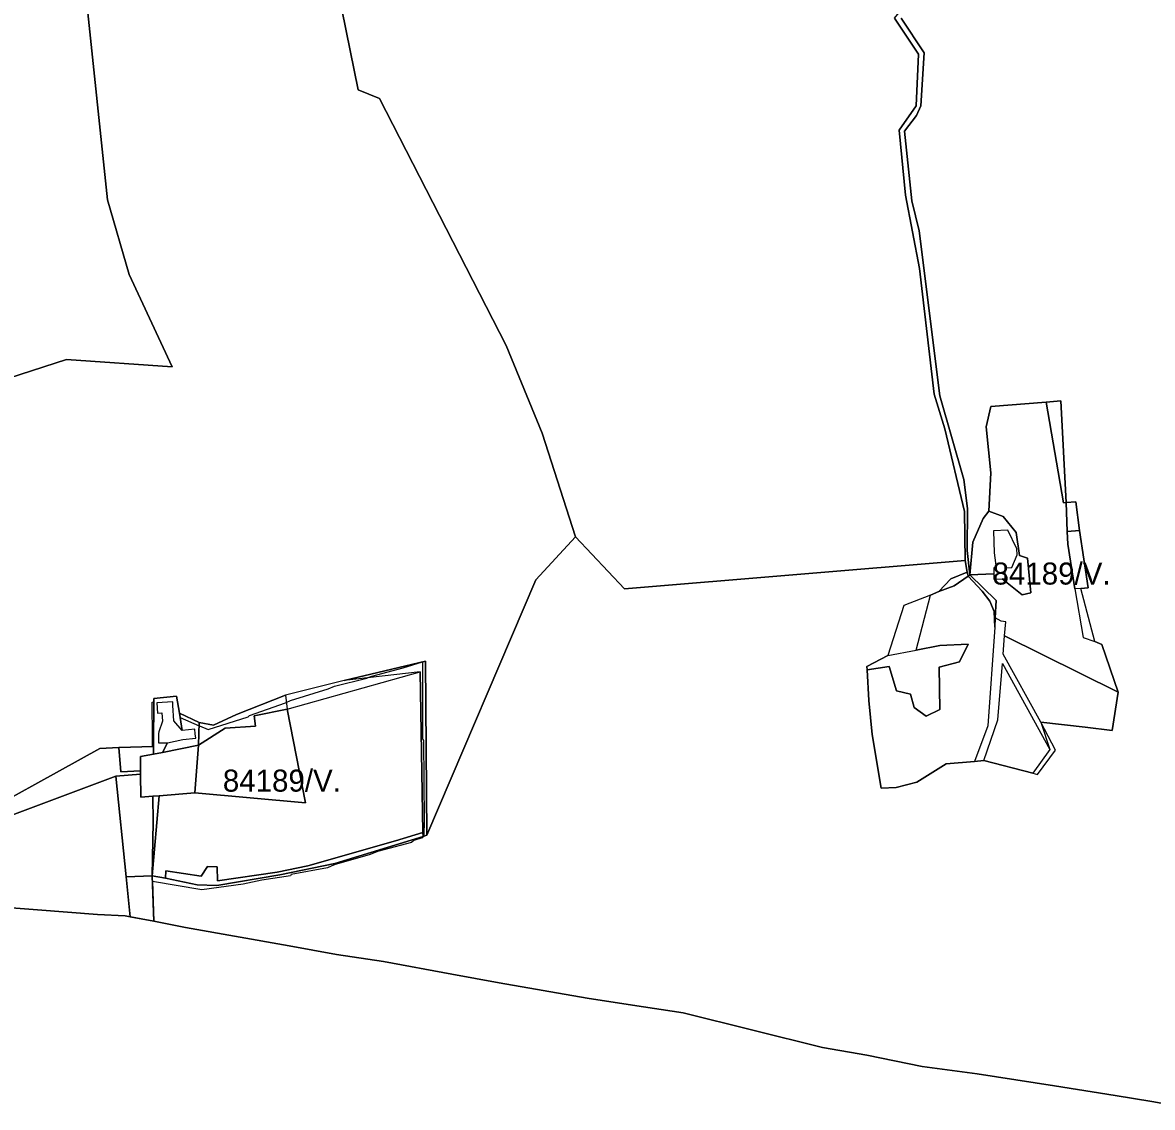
# Model space of a CAD drawing. Extents: x -477304 to -465429, y -1159113 to -1149210.
# Drawn here: x -473443 to -472675, y -1155293 to -1154555 of the extents above; entities that cross this region are included whole.
import ezdxf

# ---------------------------------------------------------------- set-up
doc = ezdxf.new("R2010")
doc.units = 0
for name, color, linetype in [('BPEJ_s', 7, 'Continuous'), ('PUPFL_s', 7, 'Continuous'), ('trav_porost_s', 7, 'Continuous'), ('voda_s', 7, 'Continuous'), ('zahrada_s', 7, 'Continuous')]:
    doc.layers.add(name, color=color, linetype=linetype)

msp = doc.modelspace()

# ---------------------------------------------------------------- linework, layer by layer
at = {"layer": 'BPEJ_s'}
msp.add_lwpolyline([(-472746.83, -1154812.93), (-472735.06, -1154881.5), (-472733.36, -1154881.36), (-472726.59, -1154880.79), (-472724.07, -1154900.37), (-472718.33, -1154939.28), (-472723.38, -1154939.7), (-472727.28, -1154940.03), (-472721.8, -1154973.13), (-472713.74, -1154975.9), (-472708.89, -1154977.79), (-472697.9, -1155010.18), (-472701.86, -1155036.25), (-472720.26, -1155034.13), (-472750.46, -1155030.58), (-472744.27, -1155049.38), (-472755.99, -1155065.45), (-472789.16, -1155056.73), (-472795.52, -1155057.36), (-472814.87, -1155058.96), (-472834.78, -1155071.44), (-472848.82, -1155075.06), (-472859.15, -1155075.63), (-472865.14, -1155039.05), (-472867.53, -1155015.89), (-472868.61, -1154995.04), (-472868.73, -1154992.77), (-472854.56, -1154985.33), (-472835.26, -1154981.63), (-472825.58, -1154944.23), (-472819.91, -1154941.84), (-472809.52, -1154937.87), (-472799.95, -1154931.38), (-472798.78, -1154930.53), (-472796.7, -1154908.14), (-472789.74, -1154892.22), (-472785.74, -1154887.11), (-472784.59, -1154861.16), (-472787.56, -1154829.87), (-472784.53, -1154816.01)], close=True, dxfattribs=at)
for points in [[(-472867.53, -1155015.89), (-472868.61, -1154995.04), (-472868.73, -1154992.77), (-472854.56, -1154985.33), (-472835.26, -1154981.63), (-472825.58, -1154944.23), (-472819.91, -1154941.84), (-472809.52, -1154937.87), (-472799.95, -1154931.38), (-472798.78, -1154930.53), (-472796.7, -1154908.14), (-472789.74, -1154892.22), (-472785.74, -1154887.11), (-472784.59, -1154861.16), (-472787.56, -1154829.87), (-472784.53, -1154816.01), (-472746.83, -1154812.93), (-472735.06, -1154881.5), (-472733.36, -1154881.36), (-472726.59, -1154880.79), (-472724.07, -1154900.37), (-472718.33, -1154939.28), (-472723.38, -1154939.7), (-472727.28, -1154940.03), (-472721.8, -1154973.13), (-472713.74, -1154975.9), (-472708.89, -1154977.79), (-472697.9, -1155010.18), (-472701.86, -1155036.25), (-472720.26, -1155034.13), (-472750.46, -1155030.58), (-472744.27, -1155049.38), (-472755.99, -1155065.45), (-472789.16, -1155056.73), (-472795.52, -1155057.36), (-472814.87, -1155058.96), (-472834.78, -1155071.44), (-472848.82, -1155075.06), (-472859.15, -1155075.63), (-472865.14, -1155039.05), (-472867.53, -1155015.89)], [(-473489.74, -1155103.39), (-473390.35, -1155048.64), (-473377.43, -1155047.9), (-473354.66, -1155047.17), (-473354.66, -1155030.8), (-473354.88, -1155027.39), (-473354.87, -1155017.03), (-473353.66, -1155016.86), (-473353.64, -1155014.55), (-473338.29, -1155012.91), (-473336.36, -1155024.64), (-473335.9, -1155027.51), (-473322.9, -1155033.08), (-473322.57, -1155033.22), (-473316.82, -1155035.69), (-473289.6, -1155026.97), (-473288.75, -1155026.12), (-473264.08, -1155017.61), (-473263.65, -1155017.4), (-473260.68, -1155015.91), (-473235.16, -1155008.04), (-473230.91, -1155006.13), (-473208.8, -1155000.81), (-473207.87, -1155000.41), (-473205.39, -1154999.33), (-473184.16, -1154993.7), (-473170.94, -1154989.74), (-473170.94, -1155042.07), (-473170.68, -1155042.5), (-473170.31, -1155043.13), (-473169.88, -1155097.56), (-473170.09, -1155107.77), (-473170.47, -1155108.3), (-473171.16, -1155109.26), (-473176.9, -1155111.17), (-473178.6, -1155112.45), (-473201.57, -1155118.62), (-473206.67, -1155120.74), (-473216.81, -1155123.64), (-473230.48, -1155127.55), (-473233.1, -1155128.64), (-473235.59, -1155129.67), (-473260.25, -1155134.35), (-473260.89, -1155135.2), (-473280.24, -1155138.18), (-473293, -1155140.94), (-473321.07, -1155144.77), (-473354.67, -1155139.1), (-473353.67, -1155166.14), (-473355.1, -1155165.87), (-473373.26, -1155162.42), (-473392.03, -1155161.46), (-473432.75, -1155158.36), (-473468.65, -1155155.71)], [(-473489.74, -1155103.39), (-473390.35, -1155048.64), (-473377.43, -1155047.9), (-473354.66, -1155047.17), (-473354.66, -1155030.8), (-473354.88, -1155027.39), (-473354.87, -1155017.03), (-473353.66, -1155016.86), (-473353.64, -1155014.55), (-473338.29, -1155012.91), (-473336.36, -1155024.64), (-473335.9, -1155027.51), (-473322.9, -1155033.08), (-473322.57, -1155033.22), (-473316.82, -1155035.69), (-473289.6, -1155026.97), (-473288.75, -1155026.12), (-473264.08, -1155017.61), (-473263.65, -1155017.4), (-473260.68, -1155015.91), (-473235.16, -1155008.04), (-473230.91, -1155006.13), (-473208.8, -1155000.81), (-473207.87, -1155000.41), (-473205.39, -1154999.33), (-473184.16, -1154993.7), (-473170.94, -1154989.74), (-473170.94, -1155042.07), (-473170.68, -1155042.5), (-473170.31, -1155043.13), (-473169.88, -1155097.56), (-473170.09, -1155107.77), (-473170.47, -1155108.3), (-473171.16, -1155109.26), (-473176.9, -1155111.17), (-473178.6, -1155112.45), (-473201.57, -1155118.62), (-473206.67, -1155120.74), (-473216.81, -1155123.64), (-473230.48, -1155127.55), (-473233.1, -1155128.64), (-473235.59, -1155129.67), (-473260.25, -1155134.35), (-473260.89, -1155135.2), (-473280.24, -1155138.18), (-473293, -1155140.94), (-473321.07, -1155144.77), (-473354.67, -1155139.1), (-473353.67, -1155166.14), (-473355.1, -1155165.87)], [(-473355.1, -1155165.87), (-473373.26, -1155162.42), (-473392.03, -1155161.46), (-473432.75, -1155158.36), (-473468.65, -1155155.71)]]:
    msp.add_lwpolyline(points, dxfattribs=at)
at = {"layer": 'PUPFL_s'}
for points in [[(-473245.06, -1154451.04), (-473214.68, -1154600.56), (-473200.2, -1154606.58), (-473114.14, -1154774.45), (-473089.68, -1154834.02), (-473067.01, -1154904.59), (-473093.82, -1154933.76), (-473168.03, -1155107.51), (-473168.97, -1154989.09), (-473224.27, -1155002.26), (-473264.22, -1155012.4), (-473297.53, -1155025.46), (-473313.06, -1155032.8), (-473322.84, -1155031.01), (-473336.36, -1155024.64), (-473338.29, -1155012.91), (-473353.64, -1155014.55), (-473353.96, -1155047.15), (-473377.43, -1155047.9), (-473390.35, -1155048.64), (-473489.74, -1155103.39)], [(-472849.91, -1154551.76), (-472833.75, -1154576.35), (-472835.17, -1154611.5), (-472846.89, -1154627.94), (-472842.6, -1154672.34), (-472833, -1154722.2), (-472823.05, -1154807.58), (-472815.87, -1154831.12), (-472802.39, -1154887.45), (-472801.98, -1154920.79), (-473033.72, -1154939.88), (-473067.01, -1154904.59), (-473089.68, -1154834.02), (-473114.14, -1154774.45), (-473200.2, -1154606.58), (-473214.68, -1154600.56), (-473245.06, -1154451.04)], [(-473484.02, -1154806.92), (-473413.02, -1154784.01), (-473341.31, -1154789.07), (-473370.58, -1154726.12), (-473385.3, -1154675.41), (-473399.61, -1154539.62), (-473454.14, -1154473.17)], [(-472838.2, -1154676.18), (-472843.27, -1154628.7), (-472834.98, -1154618.05), (-472832.18, -1154611.39), (-472829.82, -1154575.42), (-472845.56, -1154551.84)], [(-473261.67, -1155182.7), (-473332.13, -1155170.24), (-473353.67, -1155166.14), (-473354.82, -1155135.11), (-473345.7, -1155136.78), (-473324.3, -1155141.25), (-473310.8, -1155141.72), (-473268.06, -1155134.61), (-473230.58, -1155126.8), (-473170.66, -1155108.36), (-473168.03, -1155107.51), (-473093.82, -1154933.76), (-473067.01, -1154904.59), (-473033.72, -1154939.88), (-472801.98, -1154920.79), (-472800.56, -1154928.63), (-472811.79, -1154933.15), (-472819.91, -1154941.84), (-472825.58, -1154944.23), (-472843.69, -1154951.29), (-472854.56, -1154985.33), (-472868.73, -1154992.77), (-472868.61, -1154995.04), (-472867.53, -1155015.89), (-472865.14, -1155039.05), (-472859.15, -1155075.63), (-472848.82, -1155075.06), (-472834.78, -1155071.44), (-472814.87, -1155058.96), (-472795.52, -1155057.36), (-472789.16, -1155056.73), (-472755.99, -1155065.45), (-472752.72, -1155066.31), (-472740.47, -1155049.66), (-472750.46, -1155030.58), (-472720.26, -1155034.13), (-472701.86, -1155036.25), (-472697.9, -1155010.18), (-472708.89, -1154977.79), (-472713.74, -1154975.9), (-472723.38, -1154939.7), (-472718.33, -1154939.28), (-472724.07, -1154900.37), (-472726.59, -1154880.79), (-472733.36, -1154881.36), (-472736.95, -1154812.12), (-472746.83, -1154812.93), (-472784.53, -1154816.01), (-472787.56, -1154829.87), (-472784.59, -1154861.16), (-472785.74, -1154887.11), (-472789.74, -1154892.22), (-472796.7, -1154908.14), (-472798.78, -1154930.53), (-472800.66, -1154913.81), (-472800.28, -1154885.29), (-472802.86, -1154865.6), (-472819.14, -1154808.83), (-472833.22, -1154696.57), (-472838.2, -1154676.18)], [(-473465.62, -1155155.93), (-473432.75, -1155158.36), (-473392.03, -1155161.46), (-473373.26, -1155162.42), (-473369.77, -1155163.08), (-473353.67, -1155166.14), (-473332.13, -1155170.24), (-473261.67, -1155182.7), (-473229.59, -1155188.72), (-473197.58, -1155193.45), (-473151.07, -1155202.18), (-473118.88, -1155207.92), (-473059.11, -1155218.38), (-473028.17, -1155223.24), (-472993.69, -1155228.38), (-472898.88, -1155251.95), (-472868.85, -1155257.19), (-472831.14, -1155264.88), (-472793.67, -1155269.92), (-472741.29, -1155278.06), (-472700.03, -1155284.52), (-472674.94, -1155288.77), (-472652.21, -1155292.7)], [(-472652.21, -1155292.7), (-472674.94, -1155288.77), (-472700.03, -1155284.52), (-472741.29, -1155278.06), (-472793.67, -1155269.92), (-472831.14, -1155264.88), (-472868.85, -1155257.19), (-472898.88, -1155251.95), (-472993.69, -1155228.38), (-473028.17, -1155223.24), (-473059.11, -1155218.38), (-473118.88, -1155207.92), (-473151.07, -1155202.18), (-473197.58, -1155193.45), (-473229.59, -1155188.72), (-473261.67, -1155182.7)]]:
    msp.add_lwpolyline(points, dxfattribs=at)
for points in [[(-473399.61, -1154539.62), (-473385.3, -1154675.41), (-473370.58, -1154726.12), (-473341.31, -1154789.07), (-473413.02, -1154784.01), (-473484.02, -1154806.92), (-473516.79, -1154703.2), (-473541.1, -1154633.88), (-473561.76, -1154574.46), (-473562.59, -1154572.14), (-473563.43, -1154569.79), (-473570.89, -1154525.62), (-473557.02, -1154533.13), (-473530.42, -1154521.8), (-473532, -1154511.28), (-473515.98, -1154504.36), (-473508.81, -1154499.55), (-473464.56, -1154469.87), (-473457.25, -1154464.97), (-473454.14, -1154473.17)], [(-472733.36, -1154881.36), (-472735.06, -1154881.5), (-472746.83, -1154812.93), (-472736.95, -1154812.12)], [(-472819.91, -1154941.84), (-472811.79, -1154933.15), (-472800.56, -1154928.63), (-472799.95, -1154931.38), (-472809.52, -1154937.87)], [(-473170.66, -1155108.36), (-473170.85, -1155105.72), (-473172.54, -1154996.43), (-473224.27, -1155002.26), (-473168.97, -1154989.09), (-473168.03, -1155107.51)], [(-473264.22, -1155012.4), (-473263.14, -1155021.92), (-473285.46, -1155026.42), (-473284.47, -1155033.34), (-473305.26, -1155034.7), (-473323.31, -1155046.21), (-473322.84, -1155031.01), (-473313.06, -1155032.8), (-473297.53, -1155025.46)], [(-473344.49, -1155044.71), (-473333.93, -1155042.44), (-473325.27, -1155041.62), (-473325.56, -1155038.54), (-473325.85, -1155035.45), (-473334.51, -1155036.27), (-473336.36, -1155024.64), (-473322.84, -1155031.01), (-473323.31, -1155046.21), (-473347.8, -1155051.4)], [(-473170.85, -1155105.72), (-473170.66, -1155108.36), (-473230.58, -1155126.8), (-473268.06, -1155134.61), (-473310.8, -1155141.72), (-473324.3, -1155141.25), (-473345.7, -1155136.78), (-473345.46, -1155131.79), (-473321.48, -1155135.41), (-473317.34, -1155128.87), (-473310.62, -1155129.01), (-473310.38, -1155138.61), (-473269.8, -1155132.59), (-473249.1, -1155128.5), (-473189.38, -1155111.37)]]:
    msp.add_lwpolyline(points, close=True, dxfattribs=at)
at = {"layer": 'trav_porost_s'}
for points in [[(-472775.19, -1154971.86), (-472774.36, -1154962.4), (-472777.51, -1154962.02), (-472781.43, -1154959.61), (-472780.88, -1154947.93), (-472798.78, -1154930.53), (-472782.41, -1154929.87), (-472782.34, -1154933.4), (-472776.88, -1154933.29), (-472763.1, -1154944.09), (-472757.31, -1154942.71), (-472759.48, -1154919.11), (-472764.93, -1154917.28), (-472767.2, -1154901.64), (-472776.04, -1154890.85), (-472785.74, -1154887.11), (-472784.59, -1154861.16), (-472787.56, -1154829.87), (-472784.53, -1154816.01), (-472746.83, -1154812.93), (-472735.06, -1154881.5), (-472733.36, -1154881.36), (-472732.66, -1154901.1), (-472732.1, -1154909.6), (-472727.28, -1154940.03), (-472721.8, -1154973.13), (-472713.74, -1154975.9), (-472708.89, -1154977.79), (-472697.9, -1155010.18)], [(-472724.07, -1154900.37), (-472732.66, -1154901.1), (-472733.36, -1154881.36), (-472726.59, -1154880.79)], [(-472789.74, -1154892.22), (-472785.74, -1154887.11), (-472776.04, -1154890.85), (-472767.2, -1154901.64), (-472764.93, -1154917.28), (-472759.48, -1154919.11), (-472757.31, -1154942.71), (-472763.1, -1154944.09), (-472776.88, -1154933.29), (-472774.64, -1154933.25), (-472774.79, -1154925.65), (-472770.29, -1154925.56), (-472766.49, -1154916.86), (-472766.69, -1154912.72), (-472772.89, -1154900.13), (-472782.58, -1154900.55), (-472782.13, -1154915.61), (-472780.8, -1154925.77), (-472782.49, -1154925.8), (-472782.41, -1154929.87), (-472798.78, -1154930.53), (-472796.7, -1154908.14)], [(-472732.66, -1154901.1), (-472724.07, -1154900.37), (-472718.33, -1154939.28), (-472723.38, -1154939.7), (-472727.28, -1154940.03), (-472732.1, -1154909.6)], [(-472809.52, -1154937.87), (-472799.95, -1154931.38), (-472790.42, -1154941.47), (-472785.26, -1154948.37), (-472782.11, -1154955.43), (-472781.73, -1154966.08), (-472786.55, -1155033.12), (-472795.52, -1155057.36), (-472814.87, -1155058.96), (-472834.78, -1155071.44), (-472848.82, -1155075.06), (-472859.15, -1155075.63), (-472865.14, -1155039.05), (-472867.53, -1155015.89), (-472868.61, -1154995.04), (-472853.71, -1154992.88), (-472848.54, -1155009.43), (-472839.03, -1155011.58), (-472836.57, -1155020.67), (-472828.48, -1155026.62), (-472819.16, -1155022.08), (-472819.66, -1154993.18), (-472805.74, -1154989.65), (-472799.88, -1154977.61), (-472819.28, -1154978.56), (-472835.26, -1154981.63), (-472825.58, -1154944.23), (-472819.91, -1154941.84)], [(-472697.9, -1155010.18), (-472701.86, -1155036.25), (-472720.26, -1155034.13), (-472750.46, -1155030.58), (-472776.11, -1154984.39), (-472775.19, -1154971.86)], [(-472848.54, -1155009.43), (-472853.71, -1154992.88), (-472868.61, -1154995.04), (-472868.73, -1154992.77), (-472854.56, -1154985.33), (-472835.26, -1154981.63), (-472819.28, -1154978.56), (-472799.88, -1154977.61), (-472805.74, -1154989.65), (-472819.66, -1154993.18), (-472819.16, -1155022.08), (-472828.48, -1155026.62), (-472836.57, -1155020.67), (-472839.03, -1155011.58)], [(-473263.14, -1155021.92), (-473172.54, -1154996.43), (-473170.85, -1155105.72), (-473189.38, -1155111.37), (-473249.1, -1155128.5), (-473269.8, -1155132.59), (-473310.38, -1155138.61), (-473310.62, -1155129.01), (-473317.34, -1155128.87), (-473321.48, -1155135.41), (-473345.46, -1155131.79), (-473345.7, -1155136.78), (-473354.82, -1155135.11), (-473350.03, -1155080.69), (-473325.91, -1155078.7), (-473250.52, -1155085.6)], [(-472779.76, -1155029.13), (-472776.58, -1154990.67), (-472744.27, -1155049.38), (-472755.99, -1155065.45), (-472789.16, -1155056.73)], [(-473351.28, -1155024.45), (-473348.2, -1155024.3), (-473347.91, -1155030.1), (-473350.37, -1155037.3), (-473350.49, -1155038.37), (-473350.53, -1155044.67), (-473344.49, -1155044.71), (-473347.8, -1155051.4), (-473354.01, -1155052.35), (-473353.96, -1155047.15), (-473353.64, -1155014.55), (-473338.29, -1155012.91), (-473336.36, -1155024.64), (-473334.51, -1155036.27), (-473340.2, -1155029.71), (-473340.72, -1155019.32), (-473340.84, -1155016.93), (-473351.63, -1155017.47)], [(-473284.47, -1155033.34), (-473285.46, -1155026.42), (-473263.14, -1155021.92), (-473250.52, -1155085.6), (-473325.91, -1155078.7), (-473323.31, -1155046.21), (-473305.26, -1155034.7)], [(-473390.35, -1155048.64), (-473377.43, -1155047.9), (-473376.11, -1155064.37), (-473362.79, -1155063.71), (-473362.77, -1155066.06), (-473379.59, -1155067.41), (-473481.31, -1155105.45), (-473465.62, -1155155.93), (-473468.65, -1155155.71), (-473489.74, -1155103.39)], [(-473353.96, -1155047.15), (-473354.01, -1155052.35), (-473362.87, -1155053.96), (-473362.79, -1155063.71), (-473376.11, -1155064.37), (-473377.43, -1155047.9)], [(-473354.07, -1155098.6), (-473354.82, -1155135.11), (-473372.57, -1155135.85), (-473379.59, -1155067.41), (-473362.77, -1155066.06), (-473362.65, -1155081.62), (-473354.31, -1155080.93)], [(-473432.75, -1155158.36), (-473465.62, -1155155.93), (-473481.31, -1155105.45), (-473379.59, -1155067.41), (-473372.57, -1155135.85), (-473369.77, -1155163.08), (-473373.26, -1155162.42), (-473392.03, -1155161.46)], [(-473354.31, -1155080.93), (-473350.03, -1155080.69), (-473354.82, -1155135.11), (-473354.07, -1155098.6)], [(-473372.57, -1155135.85), (-473354.82, -1155135.11), (-473353.67, -1155166.14), (-473369.77, -1155163.08)]]:
    msp.add_lwpolyline(points, close=True, dxfattribs=at)
at = {"layer": 'voda_s'}
for points in [[(-472801.98, -1154920.79), (-472802.39, -1154887.45), (-472815.87, -1154831.12), (-472823.05, -1154807.58), (-472833, -1154722.2), (-472842.6, -1154672.34), (-472846.89, -1154627.94), (-472835.17, -1154611.5), (-472833.75, -1154576.35), (-472849.91, -1154551.76), (-472840.12, -1154539.39), (-472838.38, -1154537.19), (-472837.52, -1154533.23), (-472831.05, -1154503.44), (-472835.17, -1154478.9), (-472846.45, -1154462), (-472854.38, -1154455.06), (-472854.54, -1154451.8), (-472851.81, -1154446.9)], [(-472845.56, -1154551.84), (-472829.82, -1154575.42), (-472832.18, -1154611.39), (-472834.98, -1154618.05), (-472843.27, -1154628.7), (-472838.2, -1154676.18), (-472833.22, -1154696.57), (-472819.14, -1154808.83), (-472802.86, -1154865.6), (-472800.28, -1154885.29), (-472800.66, -1154913.81), (-472798.78, -1154930.53), (-472780.88, -1154947.93), (-472781.43, -1154959.61), (-472781.73, -1154966.08), (-472782.11, -1154955.43), (-472785.26, -1154948.37), (-472790.42, -1154941.47), (-472799.95, -1154931.38), (-472800.56, -1154928.63), (-472801.98, -1154920.79)]]:
    msp.add_lwpolyline(points, dxfattribs=at)
at = {"layer": 'zahrada_s'}
msp.add_lwpolyline([(-473362.87, -1155053.96), (-473354.01, -1155052.35), (-473347.8, -1155051.4), (-473323.31, -1155046.21), (-473325.91, -1155078.7), (-473350.03, -1155080.69), (-473354.31, -1155080.93), (-473362.65, -1155081.62), (-473362.77, -1155066.06), (-473362.79, -1155063.71)], close=True, dxfattribs=at)

# ---------------------------------------------------------------- texts
at = {"layer": 'BPEJ_s'}
for p in [(-472783.32, -1154937.09), (-473306.79, -1155077.94)]:
    msp.add_text('84189/V.', height=15, dxfattribs=at).set_placement(p)

doc.saveas('drawing.dxf')
